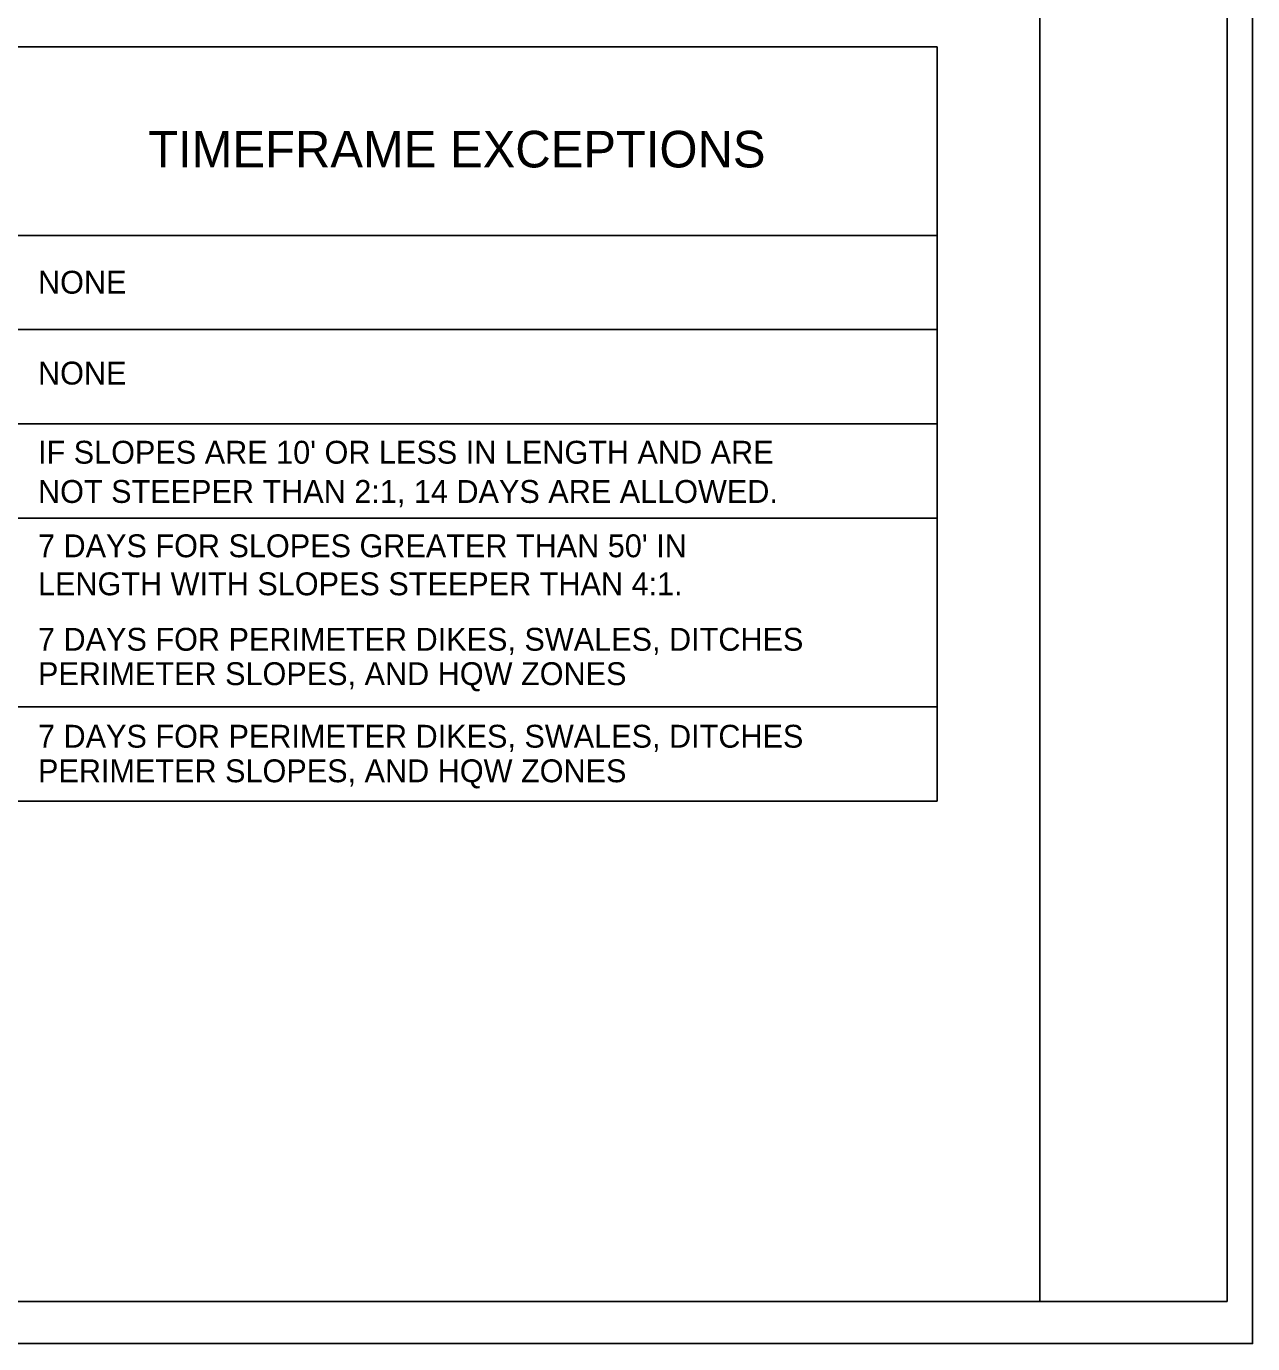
# Model space of a CAD drawing. Extents: x 1676398 to 1678098, y 1329391 to 1330491.
# Drawn here: x 1677444 to 1678098, y 1329391 to 1330094 of the extents above; entities that cross this region are included whole.
import ezdxf

# ---------------------------------------------------------------- set-up
doc = ezdxf.new("R2010")
doc.units = 0
for name, color, linetype in [('Sheet Plan CELL', 7, 'Continuous'), ('Sheet Plot Border Outside CELL', 7, 'Continuous'), ('Stabilization Guidelines Sheet CELL', 7, 'Continuous'), ('z - Construction', 7, 'Continuous')]:
    doc.layers.add(name, color=color, linetype=linetype)

msp = doc.modelspace()

# ---------------------------------------------------------------- linework, layer by layer
at = {"layer": 'Sheet Plan CELL'}
for p, q in [((1677984.81, 1329413.26), (1677984.84, 1330468.24)), ((1678084.81, 1329413.26), (1678084.84, 1330468.24)), ((1676434.81, 1329413.26), (1678084.81, 1329413.26))]:
    msp.add_line(p, q, dxfattribs=at)
at = {"layer": 'Sheet Plot Border Outside CELL'}
msp.add_lwpolyline([(1676398.36, 1330490.74), (1678098.34, 1330490.74), (1678098.34, 1329390.76), (1676398.36, 1329390.76)], close=True, dxfattribs=at)
at = {"layer": 'Stabilization Guidelines Sheet CELL'}
for p, q in [((1676490.74, 1329982.01), (1677930.05, 1329982.01)), ((1676490.74, 1329931.73), (1677930.05, 1329931.73)), ((1676490.74, 1329881.46), (1677930.05, 1329881.46)), ((1676490.74, 1329831.19), (1677930.05, 1329831.19)), ((1676490.74, 1329730.5), (1677930.05, 1329730.5)), ((1676490.74, 1329680.22), (1677930.05, 1329680.22))]:
    msp.add_line(p, q, dxfattribs=at)
msp.add_lwpolyline([(1676490.74, 1329680.22), (1676490.74, 1330082.55), (1677930.05, 1330082.55), (1677930.05, 1329680.22)], dxfattribs=at)
at = {"layer": 'z - Construction'}
for p, q in [((1678098.34, 1329390.76), (1678098.34, 1330490.74)), ((1676398.36, 1329390.76), (1678098.34, 1329390.76))]:
    msp.add_line(p, q, dxfattribs=at)

# ---------------------------------------------------------------- texts
at = {"layer": 'Stabilization Guidelines Sheet CELL'}
for s, height, p in [('TIMEFRAME EXCEPTIONS', 19.5245, (1677509.22, 1330018.28)), ('NONE', 12.209, (1677450.46, 1329950.92)), ('NONE', 12.209, (1677450.46, 1329902.46)), ("IF SLOPES ARE 10' OR LESS IN LENGTH AND ARE", 12.2089, (1677450.46, 1329860.23)), ('NOT STEEPER THAN 2:1, 14 DAYS ARE ALLOWED.', 12.2089, (1677450.46, 1329839.3)), ("7 DAYS FOR SLOPES GREATER THAN 50' IN", 12.2089, (1677450.46, 1329810.31)), ('LENGTH WITH SLOPES STEEPER THAN 4:1.', 12.2089, (1677450.46, 1329790.02)), ('7 DAYS FOR PERIMETER DIKES, SWALES, DITCHES', 12.2089, (1677450.46, 1329760.44)), ('PERIMETER SLOPES, AND HQW ZONES', 12.2089, (1677450.46, 1329742.09)), ('7 DAYS FOR PERIMETER DIKES, SWALES, DITCHES', 12.2089, (1677450.46, 1329708.71)), ('PERIMETER SLOPES, AND HQW ZONES', 12.2089, (1677450.46, 1329690.27))]:
    msp.add_text(s, height=height, rotation=359.99999, dxfattribs=at).set_placement(p)

doc.saveas('drawing.dxf')
